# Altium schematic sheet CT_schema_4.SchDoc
size 297 x 173 mm
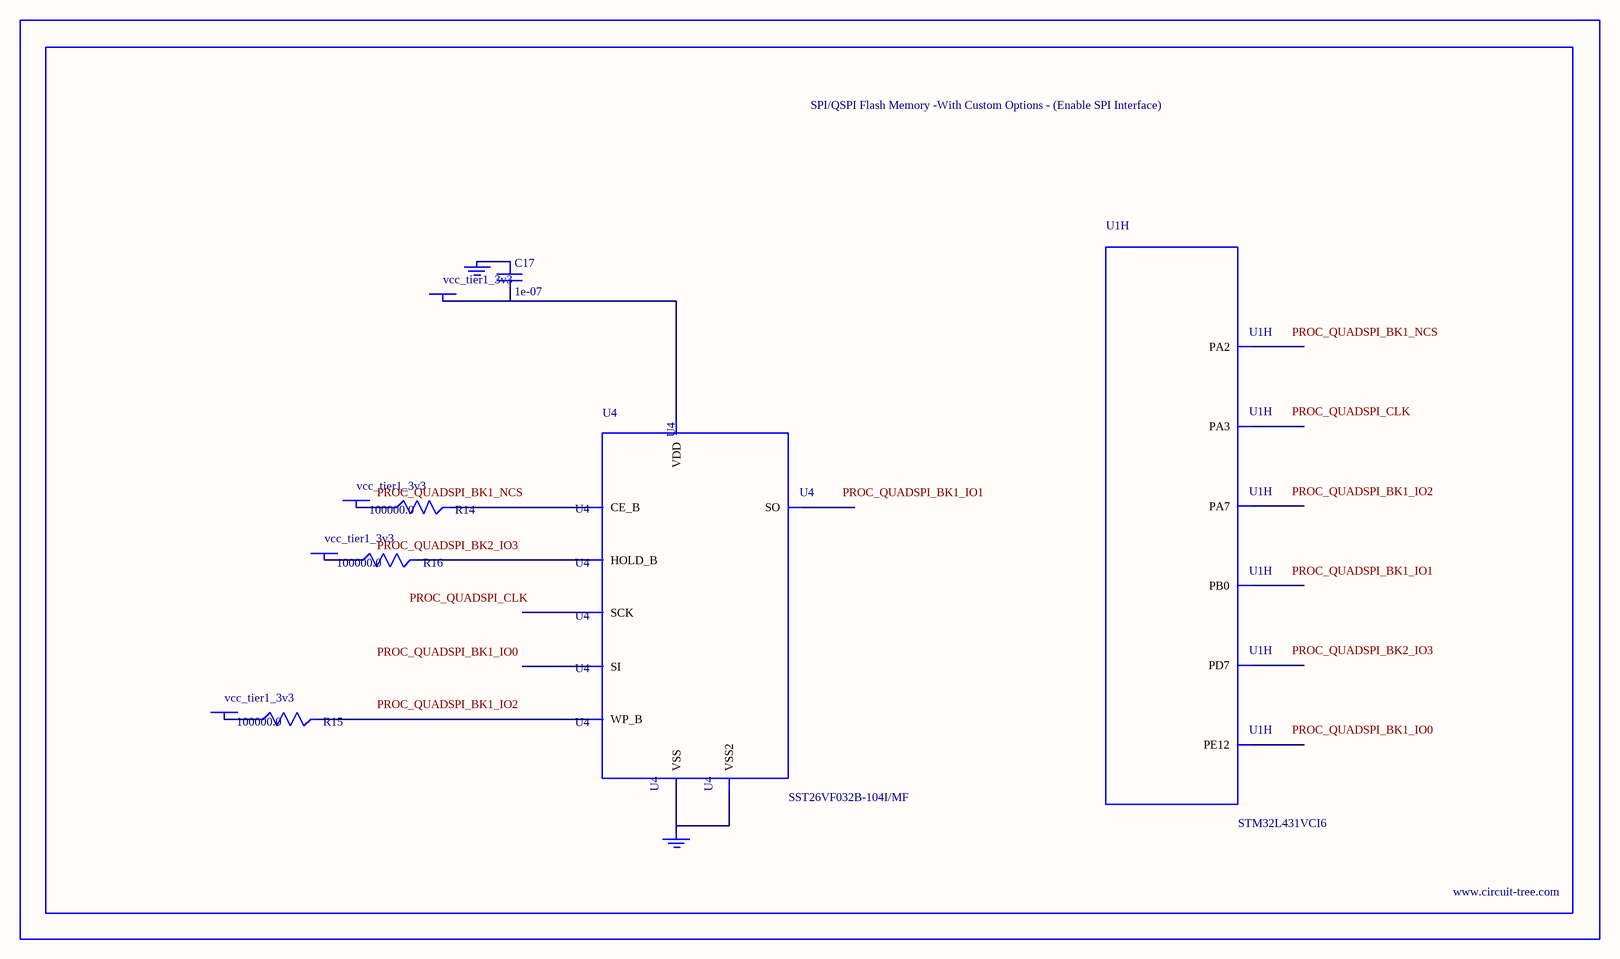
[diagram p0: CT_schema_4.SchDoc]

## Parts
BORDER3  (no value)
C17  1e-07  [C0402]
GND_INSTANCE_3_0  (no value)
GND_INSTANCE_3_1  (no value)
POWER_INSTANCE_3_0  vcc_tier1_3v3
POWER_INSTANCE_3_1  vcc_tier1_3v3
POWER_INSTANCE_3_2  vcc_tier1_3v3
POWER_INSTANCE_3_3  vcc_tier1_3v3
R14  100000.0  [R0603]
R15  100000.0  [R0603]
R16  100000.0  [R0603]
U1  STM32L431VCI6  [UFBGA100]  (part H of 9)
U4  SST26VF032B-104I/MF  [WFDN-8]

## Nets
NetC17_1: C17.1 GND_INSTANCE_3_0.0(GND)
NetC17_2: C17.2 POWER_INSTANCE_3_3.0(PWR) U4.8(VDD)
NetGND_INSTANCE_3_1_0: GND_INSTANCE_3_1.0(GND) U4.4(VSS) U4.9(VSS2)
NetPOWER_INSTANCE_3_0_0: POWER_INSTANCE_3_0.0(PWR) R14.1
NetPOWER_INSTANCE_3_1_0: POWER_INSTANCE_3_1.0(PWR) R15.1
NetPOWER_INSTANCE_3_2_0: POWER_INSTANCE_3_2.0(PWR) R16.1
NetR14_2: R14.2 U4.1(CE_B)
NetR15_2: R15.2 U4.3(WP_B)
NetR16_2: R16.2 U4.7(HOLD_B)

Not connected (* = marked no-connect by the designer): U1 A5(PD7) K3(PA2) L3(PA3) L9(PE12) M4(PA7) M5(PB0); U4 2(SO) 5(SI) 6(SCK)

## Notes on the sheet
- Labels drawn without touching a wire or pin: PROC_QUADSPI_BK1_IO0, PROC_QUADSPI_BK1_IO1, PROC_QUADSPI_BK1_IO2, PROC_QUADSPI_BK1_NCS, PROC_QUADSPI_BK2_IO3, PROC_QUADSPI_CLK

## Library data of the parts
BORDER3 = BORDER_PAGE3
C17 = C0402C104K3RACTU
GND_INSTANCE_3_0 GND_INSTANCE_3_1 = GND
POWER_INSTANCE_3_0-POWER_INSTANCE_3_3 = PWR
R14-R16 = RC0603JR-07100KL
